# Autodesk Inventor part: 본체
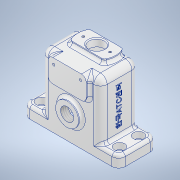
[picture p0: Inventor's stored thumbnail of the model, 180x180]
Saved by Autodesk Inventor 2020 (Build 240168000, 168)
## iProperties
Created: 2023-12
Part Number: 본체
Material: 알루미늄 6061
Document SubType Name: Modeling
Designer: oem
Density: 2.7 g/cm^3
Appearance: 알루미늄 - 평지
Mass: 217.508 g
Surface Area: 364.403 cm^2
Volume: 80.5585 cm^3
Author: oem
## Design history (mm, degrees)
sketch "스케치1"
  geometry: L1 (50, -40)-(-50, -40); L2 (-50, -40)-(-50, 0); L3 (-50, 0)-(50, 0); L4 (50, 0)-(50, -40); 2 further points
  constraints: 8 end point, 2 coincident, 2 parallel, 1 horizontal, 1 midpoint, 1 perpendicular
  dimensions: "d0" = 100 distance of L2.end L3.end; "d1" = 40 distance of L1.end L2.end
extrude "돌출1" new body sketch "스케치1" distance "d2" = 12; taper "d3" = 0 deg
sketch "스케치2"
  geometry: L1 (-50, 0)-(50, 0) reference; L2 (50, 40)-(-50, 40) reference; L3 (-31, 40)-(31, 40); L4 (31, 40)-(31, 0); L5 (31, 0)-(-31, 0); L6 (-31, 0)-(-31, 40); 6 further points
  constraints: 8 end point, 2 midpoint, 2 parallel, 1 coincident, 1 collinear, 1 horizontal, 1 perpendicular, 1 point on line
  dimensions: "d4" = 62 distance between parallel lines of L4 L6
extrude "돌출2" join sketch "스케치2" distance "d5" = 60; taper "d6" = 0 deg
sketch "스케치3"
  geometry: L1 (0, 0)-(100, 0) reference; C1 r 12 at (50, 28); 2 further points
  constraints: 1 centre point, 1 midpoint, 1 vertical alignment
  dimensions: "d7" = 24 diameter of C1; "d8" = 28 distance of C1.centre point (50, 0)
extrude "돌출3" join sketch "스케치3" distance "d9" = 4; taper "d10" = 0 deg
sketch "스케치4"
  geometry: L1 (0, 0)-(100, 0) reference; L2 (19, 72)-(81, 72) reference; L3 (30, 72)-(70, 72); L4 (70, 72)-(70, 48); L5 (70, 48)-(30, 48); L6 (30, 48)-(30, 72); 4 further points
  constraints: 8 end point, 2 midpoint, 2 parallel, 1 horizontal, 1 perpendicular, 1 point on line, 1 vertical alignment
  dimensions: "d11" = 40 distance between parallel lines of L4 L6; "d12" = 24 distance between parallel lines of L5 L2
extrude "돌출4" join sketch "스케치4" distance "d13" = 4; taper "d14" = 0 deg
sketch "스케치5"
  geometry: C1 r 12 at (50, 28) reference; C2 r 20 at (50, 28); 1 further point
  constraints: 1 centre point, 1 coincident
  dimensions: "d15" = 40 diameter of C2
extrude "돌출5" join sketch "스케치5" distance "d16" = 4; taper "d17" = 0 deg
sketch "스케치6"
  geometry: L1 (20, -4)-(-20, -4) reference; L2 (-17.321, 37)-(17.321, 37); L3 (-17.321, 17)-(17.321, 17); A1 r 20 centre (0, 27) between (-17.321, 37) and (17.321, 37); 1 further point
  constraints: 4 end point, 4 point on circle, 1 centre point, 1 horizontal, 1 vertical alignment
  dimensions: "d18" = 40 diameter of A1; "d19" = 31 distance from line of A1.centre L1; "d20" = 20 distance between parallel lines of L3 L2; "d21" = 10 distance from line of L2 A1.centre
extrude "돌출6" join sketch "스케치6" distance "d22" = 4; taper "d23" = 0 deg
sketch "스케치7"
  geometry: L1 (31, 0)-(50, 0) reference; 6 further points
  constraints: 2 horizontal alignment, 2 vertical alignment
  dimensions: "d27" = 82 distance of point (41, 30) point (-41, 30); "d28" = 20 distance of point (41, 30) point (41, 10); "d29" = 10 distance from line of point (41, 10) L1; "d30" = 41 horizontal distance of point (41, 30) point (0, 0)
hole "구멍1" sketch "스케치7" at (41, 30), (41, 10), (-41, 30), (-41, 10) diameter "d31" = 6.6; stored, may be unused: countersink angle "d35" = 90 deg, drill point angle "d37" = 118 deg; dims "d32" = 10, "d33" = 11, "d34" = 6.6, "d36" = 15
sketch "스케치8"
  geometry: C1 r 12 at (0, 0) reference; 2 further points
  constraints: 1 coincident
hole "구멍2" sketch "스케치8" at (0, 0) diameter "d38" = 13.835; stored, may be unused: countersink angle "d42" = 90 deg, drill point angle "d44" = 118 deg; dims "d39" = 8, "d40" = 11, "d41" = 6.6, "d43" = 8
sketch "스케치9"
  geometry: C1 r 20 at (0, 0) reference; C2 r 9 at (0, 0); 1 further point
  constraints: 1 centre point, 1 coincident
  dimensions: "d45" = 18 diameter of C2
extrude "돌출7" cut sketch "스케치9" distance "d46" = 8; taper "d47" = 0 deg
sketch "스케치10"
  geometry: L1 (50, 0)-(50, -40) reference; L2 (-50, 0)-(50, 0) reference; L3 (-27, -4)-(27, -4); L4 (27, -4)-(27, -36); L5 (27, -36)-(-27, -36); L6 (-27, -36)-(-27, -4); 9 further points
  constraints: 8 end point, 4 midpoint, 2 parallel, 1 horizontal, 1 horizontal alignment, 1 perpendicular, 1 vertical alignment
  dimensions: "d48" = 32 distance between parallel lines of L5 L3; "d49" = 54 distance between parallel lines of L4 L6
extrude "돌출8" cut sketch "스케치10" distance "d50" = 68; taper "d51" = 0 deg
sketch "스케치11"
  geometry: C1 r 8 at (0, 27); A1 r 20 centre (0, 27) between (17.321, 17) and (17.321, 37) reference; 1 further point
  constraints: 1 centre point, 1 coincident
  dimensions: "d52" = 16 diameter of C1
extrude "돌출9" cut sketch "스케치11" distance "d53" = 68; taper "d54" = 0 deg
sketch "스케치12"
  geometry: C1 r 9 at (0, 0) reference; C2 r 20 at (0, 0) reference; A1 r 15 centre (0, 0) between (0, 15) and (-15, 0); 3 further points
  constraints: 4 point on circle, 2 horizontal alignment, 2 vertical alignment, 1 centre point, 1 coincident
  dimensions: "d55" = 30 diameter of A1
hole "구멍3" sketch "스케치12" at (0, 15), (-15, 0), (0, -15), (15, 0) diameter "d56" = 2.459; stored, may be unused: countersink angle "d60" = 90 deg, drill point angle "d62" = 118 deg; dims "d57" = 9, "d58" = 11, "d59" = 6.6, "d61" = 9
sketch "스케치13"
  geometry: L1 (70, 72)-(30, 72) reference; 5 further points
  constraints: 1 horizontal alignment
  dimensions: "d63" = 28 distance of point (64, 66) point (36, 66); "d64" = 14 horizontal distance of point (50, 0) point (64, 66); "d65" = 6 distance from line of point (64, 66) L1
hole "구멍4" sketch "스케치13" at (36, 66), (64, 66) diameter "d66" = 2.459; stored, may be unused: countersink angle "d70" = 90 deg, drill point angle "d72" = 118 deg; dims "d67" = 9, "d68" = 11, "d69" = 6.6, "d71" = 9
sketch "스케치14"
  geometry: L1 (20, -4)-(15, -4) reference; C1 r 8 at (0, 27) reference; 3 further points
  constraints: 1 horizontal alignment
  dimensions: "d73" = 28 distance of point (14, 27) point (-14, 27); "d74" = 14 distance of point (-14, 27) C1.centre; "d75" = 31 distance from line of point (14, 27) L1
hole "구멍5" sketch "스케치14" at (-14, 27), (14, 27) diameter "d76" = 2.459; stored, may be unused: countersink angle "d80" = 90 deg, drill point angle "d82" = 118 deg; dims "d77" = 9, "d78" = 11, "d79" = 6.6, "d81" = 9
node "작업 평면1"
sketch "스케치15"
  geometry: L1 (-4, 28)-(-4, 4) reference; L2 (4, -12)-(36, -12) reference; 2 further points
  constraints: 1 other
  dimensions: "d84" = 23 distance from line of point (19, 28) L1; "d85" = 40 distance from line of point (19, 28) L2
feature "엠보싱1" sketch "스케치15" dims "d0" = 100, "d1" = 40, "d86" = 0.5, "d87" = 0
fillet "모깎기10" dims "d94" = 7
fillet "모깎기12" dims "d96" = 7
fillet "모깎기13" dims "d97" = 3
fillet "모깎기14" dims "d98" = 3
fillet "모깎기16" dims "d100" = 7
fillet "모깎기17" dims "d101" = 3
fillet "모깎기19" dims "d103" = 3
fillet "모깎기20" dims "d104" = 3
chamfer "모따기1" distance "d105" = 1; stored, may be unused: second distance "d106" = 2, angle "d107" = 45 deg
fillet "모깎기21" dims "d108" = 3
fillet "모깎기22" dims "d109" = 5
fillet "모깎기23" dims "d110" = 3
chamfer "모따기2" distance "d111" = 1; stored, may be unused: second distance "d112" = 2, angle "d113" = 45 deg
node "솔리드1"
feature "A9D066F2-1C7D-4E18-AEED-F7BC21143FA4" dims "d31" = 6.6, "d32" = 10, "d33" = 11, "d34" = 6.6, "d35" = 90 deg, "d36" = 15, "d37" = 118 deg
other parameters: "d83" = 5
